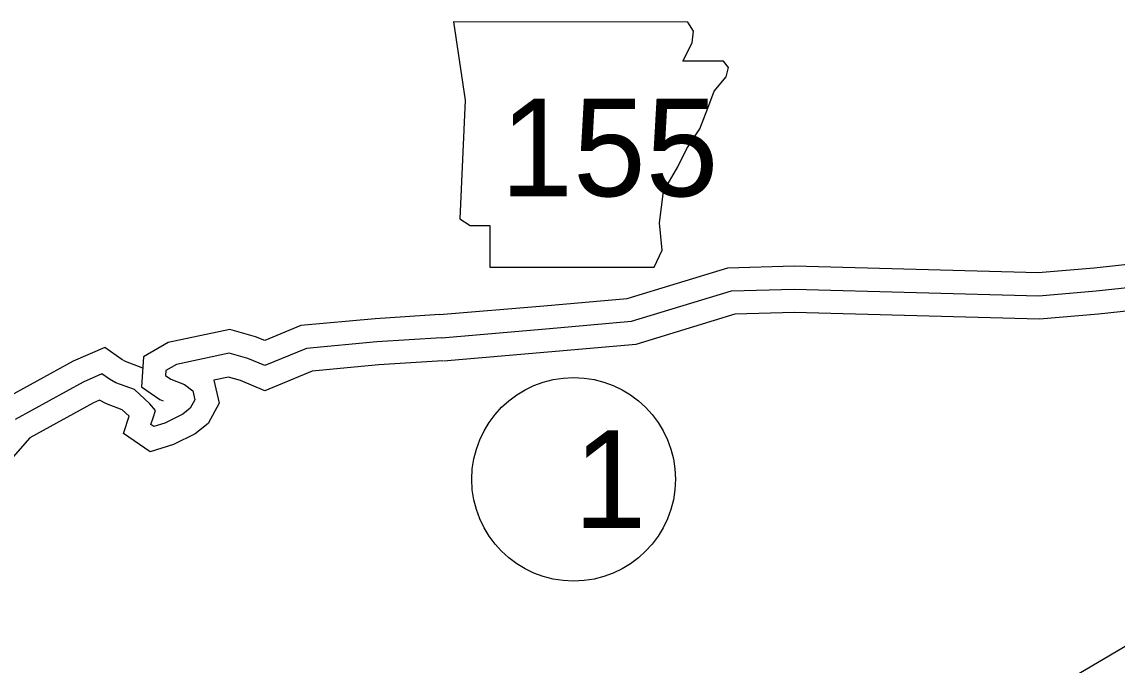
# Model space of a CAD drawing. Extents: x -83719 to 153526, y -11835 to 11446.
# Drawn here: x -2491.8 to -2255.2, y 787.2 to 926.2 of the extents above; entities that cross this region are included whole.
import ezdxf

# ---------------------------------------------------------------- set-up
doc = ezdxf.new("R2010")
doc.units = 0
for name, color, linetype in [('Level 10', 7, 'Continuous'), ('Level 11', 7, 'Continuous'), ('Level 21', 7, 'Continuous'), ('Level 27', 7, 'Continuous'), ('Level 59', 7, 'Continuous')]:
    doc.layers.add(name, color=color, linetype=linetype)

msp = doc.modelspace()

# ---------------------------------------------------------------- linework, layer by layer
at = {"layer": 'Level 10'}
for points in [[(-2401.6, 862.95), (-2379.04, 864.89), (-2361.02, 866.46), (-2339.29, 873.09), (-2324.96, 873.48), (-2272.22, 872.05), (-2260.13, 873.06), (-2237.74, 875.51), (-2227.07, 875.61), (-2192.19, 871.87), (-2149.27, 867.82), (-2130.26, 865.05), (-2129.58, 864.93)], [(-2400.74, 852.99), (-2378.18, 854.93), (-2359.11, 856.59), (-2337.66, 863.13), (-2324.96, 863.48), (-2271.94, 862.04), (-2259.17, 863.1), (-2237.14, 865.51), (-2227.56, 865.61), (-2193.19, 861.92), (-2150.46, 857.89), (-2131.79, 855.16), (-2125.8, 854.17)], [(-2160.77, 830.84), (-2176.55, 827.38), (-2184.46, 824.74), (-2199.92, 819.04), (-2207.84, 815.21), (-2217.92, 808.73), (-2222.81, 805.72), (-2245.69, 795.8), (-2264.65, 784.59), (-2271.07, 779.68), (-2277.66, 773.56), (-2290.85, 760.5), (-2302.09, 748.61), (-2310.01, 740.45), (-2316.07, 735.52), (-2319.28, 733.06), (-2325.34, 729.26), (-2327.28, 728.11), (-2332.55, 723.51), (-2335.76, 719.18), (-2345.42, 700.66)]]:
    msp.add_lwpolyline(points, dxfattribs=at)
at = {"layer": 'Level 11'}
for points in [[(-2401.49, 862.96), (-2415.49, 862.07), (-2431.57, 860.58), (-2439.33, 857.35), (-2441.32, 858.19), (-2446.87, 859.75), (-2460.25, 856.92), (-2465.54, 853.84), (-2465.97, 847.33), (-2462.02, 844.59), (-2461.3, 844.3)], [(-2465.72, 851.41), (-2469.44, 852.8), (-2470.27, 853.25), (-2473.91, 855.87), (-2480.78, 852.89), (-2496.47, 844.23)], [(-2400.85, 852.98), (-2414.71, 852.1), (-2429.13, 850.76), (-2439.34, 846.51), (-2444.63, 848.73), (-2447.22, 849.46), (-2450.33, 848.8), (-2449.17, 843.81), (-2451.55, 839.44), (-2454.39, 837.21), (-2459.05, 834.88), (-2464.14, 833.29), (-2469.87, 837.27), (-2468.63, 840.98), (-2470.19, 842.41), (-2473.57, 843.67), (-2475.06, 844.47), (-2476.36, 843.9), (-2490.12, 836.31)], [(-2490.11, 836.32), (-2494.76, 831.06)]]:
    msp.add_lwpolyline(points, dxfattribs=at)
at = {"layer": 'Level 21'}
msp.add_lwpolyline([(-2398.6, 926.21), (-2396.07, 909.3), (-2397.19, 883.64), (-2394.94, 882.23), (-2390.71, 882.23), (-2390.71, 873.2), (-2355.18, 873.2), (-2353.49, 876.87), (-2354.05, 882.79), (-2353.21, 889.56), (-2350.11, 894.92), (-2348.13, 898.86), (-2345.31, 903.09), (-2343.62, 907.6), (-2342.21, 911.27), (-2339.67, 914.37), (-2339.11, 916.35), (-2340.24, 917.76), (-2348.98, 917.76), (-2347, 921.7), (-2346.72, 924.24), (-2347.89, 926.19)], close=True, dxfattribs=at)
at = {"layer": 'Level 27'}
msp.add_circle((-2372.61, 827.37), 22, dxfattribs=at)
at = {"layer": 'Level 59'}
for points in [[(-2401.17, 857.97), (-2378.61, 859.91), (-2360.07, 861.53), (-2338.47, 868.11), (-2324.96, 868.48), (-2272.08, 867.04), (-2259.65, 868.08), (-2237.44, 870.51), (-2227.31, 870.61), (-2192.69, 866.89), (-2149.86, 862.85), (-2131.03, 860.1), (-2121.75, 858.58)], [(-2401.17, 857.97), (-2415.1, 857.09), (-2430.35, 855.67), (-2439.33, 851.93), (-2442.98, 853.46), (-2447.04, 854.61), (-2458.43, 852.2), (-2460.72, 850.86), (-2460.79, 849.82), (-2459.64, 849.02), (-2456.7, 847.84), (-2454.93, 846.52), (-2454.47, 844.53), (-2455.45, 842.73), (-2457.08, 841.45), (-2460.92, 839.53), (-2463.3, 838.79), (-2463.94, 839.24), (-2463.48, 840.62), (-2462.93, 842.21), (-2464.18, 843.68), (-2467.53, 846.75), (-2471.51, 848.24), (-2472.93, 848.99), (-2474.53, 850.15), (-2478.57, 848.39), (-2493.29, 840.27)]]:
    msp.add_lwpolyline(points, dxfattribs=at)

# ---------------------------------------------------------------- texts
at = {"layer": 'Level 21'}
msp.add_text('155', height=21.12, dxfattribs=at).set_placement((-2388.44, 888.54))
at = {"layer": 'Level 27'}
msp.add_text('1', height=21.12, dxfattribs=at).set_placement((-2372.61, 816.81))

doc.saveas('drawing.dxf')
